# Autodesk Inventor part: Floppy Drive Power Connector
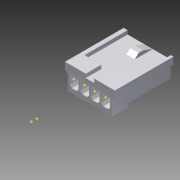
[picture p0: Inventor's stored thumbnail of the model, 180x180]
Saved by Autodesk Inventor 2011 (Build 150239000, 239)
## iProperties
Company: Autodesk Inc.
Created: 2006-09
Part Number: Floppy Drive Power Connector
Document SubType Name: Modeling
Designer: Autodesk Inc.
Density: 1 g/cm^3
Categories: <MemberInstance><Categories><Category DisplayName="" Mnemonic="CABLEANDHARNESS" InternalName="e4a7e005-5e42-4d16-b293-125e7f0d0512"><Category DisplayName="" Mne
Mass: 0.435998 g
Surface Area: 10.9492 cm^2
Volume: 0.435998 cm^3
Author: Autodesk Inc.
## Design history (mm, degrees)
feature "Base1"
sketch "Sketch1"
  geometry: L1 (-0.283, -0.51)-(0.038, -0.51) reference; L2 (0.038, -0.51)-(0.063, -0.456) reference; L3 (0.063, -0.456)-(0.322, -0.456) reference; L4 (0.322, -0.456)-(0.348, -0.51) reference; L5 (0.348, -0.51)-(0.668, -0.51) reference; L6 (0.668, -0.51)-(0.385, 0) reference; L7 (0.385, 0)-(0, 0) reference; L8 (0, 0)-(-0.283, -0.51) reference; L9 (-0.712, 0.026)-(2.921, 0.026); L10 (2.921, 0.026)-(2.921, -0.562); L11 (2.921, -0.562)-(-0.712, -0.562); L12 (-0.712, -0.562)-(-0.712, 0.026); L13 (0.367, 2.69)-(0.367, 4.74) reference; L14 (-0.383, 2.69)-(0.367, 2.69) reference; L15 (-0.383, 0.29)-(-0.383, 2.69) reference; L16 (2.017, 0.29)-(-0.383, 0.29) reference; L17 (2.017, 2.69)-(2.017, 0.29) reference; L18 (1.267, 2.69)-(2.017, 2.69) reference; L19 (1.267, 3.84)-(1.267, 2.69) reference; L20 (2.367, 3.84)-(1.267, 3.84) reference; L21 (2.367, 1.24)-(2.367, 3.84) reference; L22 (3.017, 0.59)-(2.367, 1.24) reference; L23 (3.017, -1.01)-(3.017, 0.59) reference; L24 (2.067, -1.01)-(3.017, -1.01) reference; L25 (2.067, -0.11)-(2.067, -1.01) reference; L26 (-1.933, -0.11)-(2.067, -0.11) reference; L27 (-1.933, -0.11)-(-3.933, -0.11) reference; L28 (-8.233, -0.11)-(-3.933, -0.11) reference; L29 (-8.233, -1.01)-(-8.233, -0.11) reference; L30 (-8.883, -1.01)-(-8.233, -1.01) reference; L31 (-8.883, 0.59)-(-8.883, -1.01) reference; L32 (-8.233, 1.24)-(-8.883, 0.59) reference; L33 (-8.233, 3.84)-(-8.233, 1.24) reference; L34 (-7.133, 3.84)-(-8.233, 3.84) reference; L35 (-7.133, 3.84)-(-7.133, 2.69) reference; L36 (-7.883, 2.69)-(-7.133, 2.69) reference; L37 (-7.883, 0.29)-(-7.883, 2.69) reference; L38 (-5.483, 0.29)-(-7.883, 0.29) reference; L39 (-5.483, 2.69)-(-5.483, 0.29) reference; L40 (-6.233, 2.69)-(-5.483, 2.69) reference; L41 (-6.233, 3.84)-(-6.233, 2.69) reference; L42 (-4.633, 3.84)-(-6.233, 3.84) reference; L43 (-4.633, 3.84)-(-4.633, 2.69) reference; L44 (-5.383, 2.69)-(-4.633, 2.69) reference; L45 (-5.383, 0.29)-(-5.383, 2.69) reference; L46 (-2.983, 0.29)-(-5.383, 0.29) reference; L47 (-2.983, 2.69)-(-2.983, 0.29) reference; L48 (-3.733, 2.69)-(-2.983, 2.69) reference; L49 (-3.733, 3.84)-(-3.733, 2.69) reference; L50 (-2.133, 3.84)-(-3.733, 3.84) reference; L51 (-2.133, 3.84)-(-2.133, 2.69) reference; L52 (-2.883, 2.69)-(-2.133, 2.69) reference; L53 (-2.883, 0.29)-(-2.883, 2.69) reference; L54 (-0.483, 0.29)-(-2.883, 0.29) reference; L55 (-0.483, 2.69)-(-0.483, 0.29) reference; L56 (-1.233, 2.69)-(-0.483, 2.69) reference; L57 (-1.233, 4.74)-(-1.233, 2.69) reference; L58 (-1.233, 4.74)-(0.367, 4.74) reference; 12 further points
  constraints: 8 end point, 8 midpoint, 4 horizontal alignment, 4 vertical alignment, 2 parallel, 1 horizontal, 1 perpendicular
  node "Projected Loop1"
extrude "Extrusion1" cut sketch "Sketch1" stored distance "d0" = 10; taper "d1" = 0 deg
node "1"
node "2"
node "3"
node "4"
workplane "Work Plane1"
workplane "Work Plane2"
sketch "Sketch2"
  geometry: L1 (4.05, -3.25)-(6.55, -3.25); 1 further point
  constraints: 2 end point, 1 horizontal, 1 midpoint
workpoint "Work Point5"
sketch "Sketch3"
  geometry: 1 further point
workpoint "Work Point6"
body "Solid1"
other parameters: "d2" = 12.7, "d3" = 13.97
